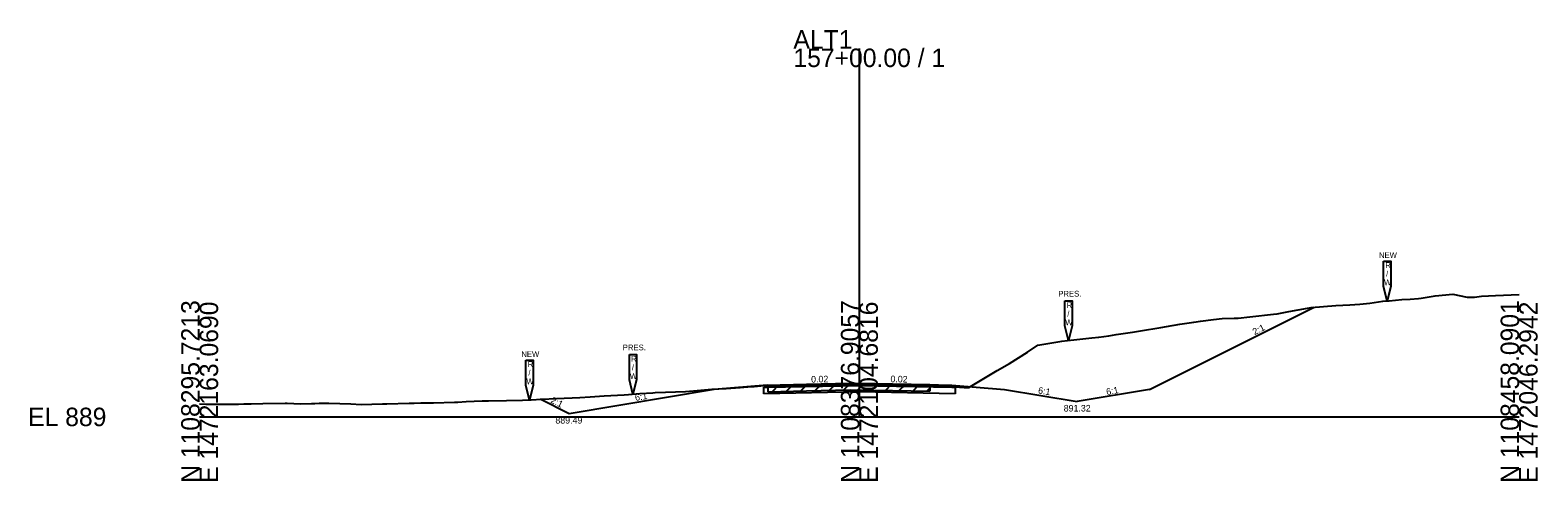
# Model space of a CAD drawing. Extents: x -26 to 2203, y -10 to 19568.
# Drawn here: x -25.7 to 202.8, y 18990.3 to 19058.6 of the extents above; entities that cross this region are included whole.
import ezdxf

# ---------------------------------------------------------------- set-up
doc = ezdxf.new("R2010")
doc.units = 0
for name, color, linetype in [('RD_GPK_XS_Cell', 7, 'Continuous'), ('RD_XS_Base', 7, 'Continuous'), ('RD_XS_ExGround', 7, 'Continuous'), ('RD_XS_ExPaveRet', 7, 'Continuous'), ('RD_XS_ExRW', 7, 'Continuous'), ('RD_XS_Greenside', 7, 'Continuous'), ('RD_XS_NewRW', 7, 'Continuous'), ('RD_XS_Pave', 7, 'Continuous'), ('RD_XS_TieSlope', 7, 'Continuous'), ('RD_XS_TX_Slope', 7, 'Continuous')]:
    doc.layers.add(name, color=color, linetype=linetype)

msp = doc.modelspace()

# ---------------------------------------------------------------- linework, layer by layer
at = {"layer": 'RD_GPK_XS_Cell'}
for p, q in [((100, 19000), (100, 19055.84)), ((0, 19000), (100, 19000)), ((100, 19000), (200, 19000))]:
    msp.add_line(p, q, dxfattribs=at)
at = {"layer": 'RD_XS_Base'}
for points in [[(85.5, 19004.49), (86, 19004.5), (100, 19004.78), (114, 19004.5), (114.5, 19004.49)], [(85.5, 19003.49), (85.5, 19004.49)], [(114.5, 19003.49), (100, 19003.78), (85.5, 19003.49)], [(114.5, 19004.49), (114.5, 19003.49)]]:
    msp.add_lwpolyline(points, dxfattribs=at)
at = {"layer": 'RD_XS_ExGround'}
msp.add_lwpolyline([(0, 19001.96), (0.92, 19001.95), (2.19, 19001.95), (2.69, 19001.95), (5.89, 19001.95), (6.7, 19001.96), (7.83, 19002), (9.58, 19002.01), (12.96, 19002.06), (13.28, 19002.06), (15.3, 19001.98), (16.97, 19002.04), (17.44, 19002.03), (18.1, 19002.07), (19.59, 19002.06), (22.9, 19001.97), (24.49, 19001.88), (27.71, 19001.96), (28.38, 19001.98), (31.75, 19002.08), (32.49, 19002.1), (33.52, 19002.11), (34.64, 19002.15), (35.45, 19002.15), (38.65, 19002.24), (39.14, 19002.26), (40.4, 19002.32), (42.84, 19002.44), (43.79, 19002.46), (46.53, 19002.5), (48.93, 19002.56), (50.23, 19002.6), (51.84, 19002.71), (54.07, 19002.77), (57.62, 19002.92), (59.21, 19003.04), (61.32, 19003.2), (64.34, 19003.37), (65.01, 19003.41), (66.72, 19003.53), (68.71, 19003.66), (69.03, 19003.68), (70.6, 19003.75), (73.63, 19003.86), (74.85, 19003.97), (77.63, 19004.2), (79.79, 19004.32), (81.93, 19004.47), (82.5, 19004.5), (83.11, 19004.56), (84.05, 19004.61), (86.11, 19004.79), (91.96, 19004.95), (98.62, 19005.11), (100, 19005.09), (105.04, 19005.01), (110.66, 19004.91), (114.49, 19004.58), (115.87, 19004.45), (116.61, 19004.45), (120.86, 19007.05), (122.77, 19008.12), (125.46, 19009.84), (127.07, 19010.87), (130.7, 19011.46), (131.53, 19011.59), (132.52, 19011.7), (135.22, 19011.97), (136.28, 19012.11), (137.81, 19012.27), (138.92, 19012.47), (141.42, 19012.86), (142.61, 19013.05), (145.68, 19013.57), (146.55, 19013.72), (148.56, 19014.04), (150, 19014.25), (150.71, 19014.38), (151.69, 19014.53), (153.7, 19014.78), (155.01, 19014.9), (156.83, 19014.95), (157.39, 19014.98), (159.2, 19015.18), (162.78, 19015.57), (163.34, 19015.65), (165.09, 19015.99), (167.9, 19016.51), (168.48, 19016.58), (172.24, 19016.87), (174.35, 19016.98), (175.87, 19017.11), (177.38, 19017.27), (179.32, 19017.55), (180.28, 19017.62), (182.21, 19017.8), (183.5, 19017.86), (184.73, 19017.96), (185.14, 19018), (187.29, 19018.35), (189.97, 19018.61), (192.12, 19018.16), (193.24, 19018.18), (194.28, 19018.29), (196.44, 19018.39), (200, 19018.56)], dxfattribs=at)
at = {"layer": 'RD_XS_ExPaveRet'}
for p, q in [((86.11, 19004.79), (86.11, 19003.8)), ((86.11, 19004.79), (86.11, 19003.79)), ((86.78, 19003.82), (87.8, 19004.84)), ((88.96, 19003.88), (89.98, 19004.9)), ((91.14, 19003.93), (92.16, 19004.96)), ((93.32, 19003.99), (94.34, 19005.01)), ((95.49, 19004.04), (96.51, 19005.06)), ((97.66, 19004.1), (98.68, 19005.11)), ((99.79, 19004.1), (100.77, 19005.08)), ((101.88, 19004.06), (102.86, 19005.04)), ((103.96, 19004.03), (104.94, 19005.01)), ((106.05, 19003.99), (107.03, 19004.97)), ((108.13, 19003.96), (109.11, 19004.94)), ((110.66, 19004.91), (110.66, 19003.92)), ((110.66, 19004.91), (110.66, 19003.91)), ((110.22, 19003.92), (110.66, 19004.37))]:
    msp.add_line(p, q, dxfattribs=at)
msp.add_lwpolyline([(86.11, 19003.8), (91.98, 19003.96), (98.62, 19004.12), (105.02, 19004.01), (110.66, 19003.92)], dxfattribs=at)
at = {"layer": 'RD_XS_ExRW'}
for points in [[(131.14, 19017.62), (132.23, 19017.62), (132.23, 19013.79), (131.69, 19011.6), (131.14, 19013.79)], [(65.13, 19009.47), (66.22, 19009.47), (66.22, 19005.64), (65.68, 19003.45), (65.13, 19005.64)]]:
    msp.add_lwpolyline(points, close=True, dxfattribs=at)
at = {"layer": 'RD_XS_Greenside'}
for points in [[(86, 19004.82), (78, 19004.15)], [(114, 19004.82), (122, 19004.15)], [(78, 19004.15), (56, 19000.49)], [(122, 19004.15), (133, 19002.32)], [(144, 19004.15), (133, 19002.32)]]:
    msp.add_lwpolyline(points, dxfattribs=at)
at = {"layer": 'RD_XS_NewRW'}
for points in [[(179.45, 19023.62), (180.55, 19023.62), (180.55, 19019.79), (180, 19017.61), (179.45, 19019.79)], [(49.45, 19008.61), (50.55, 19008.61), (50.55, 19004.78), (50, 19002.59), (49.45, 19004.78)]]:
    msp.add_lwpolyline(points, close=True, dxfattribs=at)
at = {"layer": 'RD_XS_Pave'}
for points in [[(86, 19004.82), (88, 19004.86), (100, 19005.1), (112, 19004.86), (114, 19004.82)], [(86, 19004.66), (100, 19004.94), (114, 19004.66)], [(114, 19004.66), (100, 19004.94), (86, 19004.66)], [(86, 19004.66), (86, 19004.82)], [(114, 19004.5), (100, 19004.78), (86, 19004.5)], [(114, 19004.82), (114, 19004.66)], [(86, 19004.5), (86, 19004.66)], [(114, 19004.66), (114, 19004.5)]]:
    msp.add_lwpolyline(points, dxfattribs=at)
at = {"layer": 'RD_XS_TieSlope'}
for points in [[(144, 19004.15), (168.92, 19016.62)], [(56, 19000.49), (51.59, 19002.69)]]:
    msp.add_lwpolyline(points, dxfattribs=at)

# ---------------------------------------------------------------- texts
at = {"layer": 'RD_GPK_XS_Cell'}
for s, p in [('ALT1', (90, 19055.84)), ('157+00.00 / 1', (90, 19053.04)), ('EL 889', (-26, 18998.6))]:
    msp.add_text(s, height=2.8, dxfattribs=at).set_placement(p)
for s, p in [('N 1108295.7213', (0, 18990)), ('E 1472163.0690', (2.8, 18990)), ('N 1108376.9057', (100, 18990)), ('E 1472104.6816', (102.8, 18990)), ('N 1108458.0901', (200, 18990)), ('E 1472046.2942', (202.8, 18990))]:
    msp.add_text(s, height=2.8, rotation=90, dxfattribs=at).set_placement(p)
at = {"layer": 'RD_XS_ExRW'}
for s, p in [('PRES.', (130.14, 19018.24)), ('R', (131.4, 19016.52)), ('W', (131.21, 19013.9)), ('/', (131.52, 19015.21)), ('PRES.', (64.13, 19010.09)), ('R', (65.39, 19008.38)), ('/', (65.51, 19007.06)), ('W', (65.21, 19005.75))]:
    msp.add_text(s, height=0.875, dxfattribs=at).set_placement(p)
at = {"layer": 'RD_XS_NewRW'}
for s, p in [('NEW', (178.75, 19024.1)), ('R', (179.71, 19022.58)), ('W', (179.53, 19019.96)), ('/', (179.83, 19021.27)), ('NEW', (48.75, 19009.09)), ('R', (49.71, 19007.57)), ('/', (49.83, 19006.26)), ('W', (49.53, 19004.95))]:
    msp.add_text(s, height=0.875, dxfattribs=at).set_placement(p)
at = {"layer": 'RD_XS_TX_Slope'}
for s, rotation, p in [('2:1', 26.5651, (159.91, 19012.39)), ('0.02', 1.1458, (92.69, 19005.2)), ('0.02', 358.8542, (104.7, 19005.26)), ('2:1', 333.4349, (53.11, 19002.21)), ('6:1', 9.4642, (66.07, 19002.42)), ('6:1', 350.5358, (127.04, 19003.57)), ('6:1', 10.416, (137.51, 19003.29))]:
    msp.add_text(s, height=1, rotation=rotation, dxfattribs=at).set_placement(p)
for s, p in [('891.32', (130.97, 19000.82)), ('889.49', (53.92, 18998.99))]:
    msp.add_text(s, height=1, dxfattribs=at).set_placement(p)

doc.saveas('drawing.dxf')
